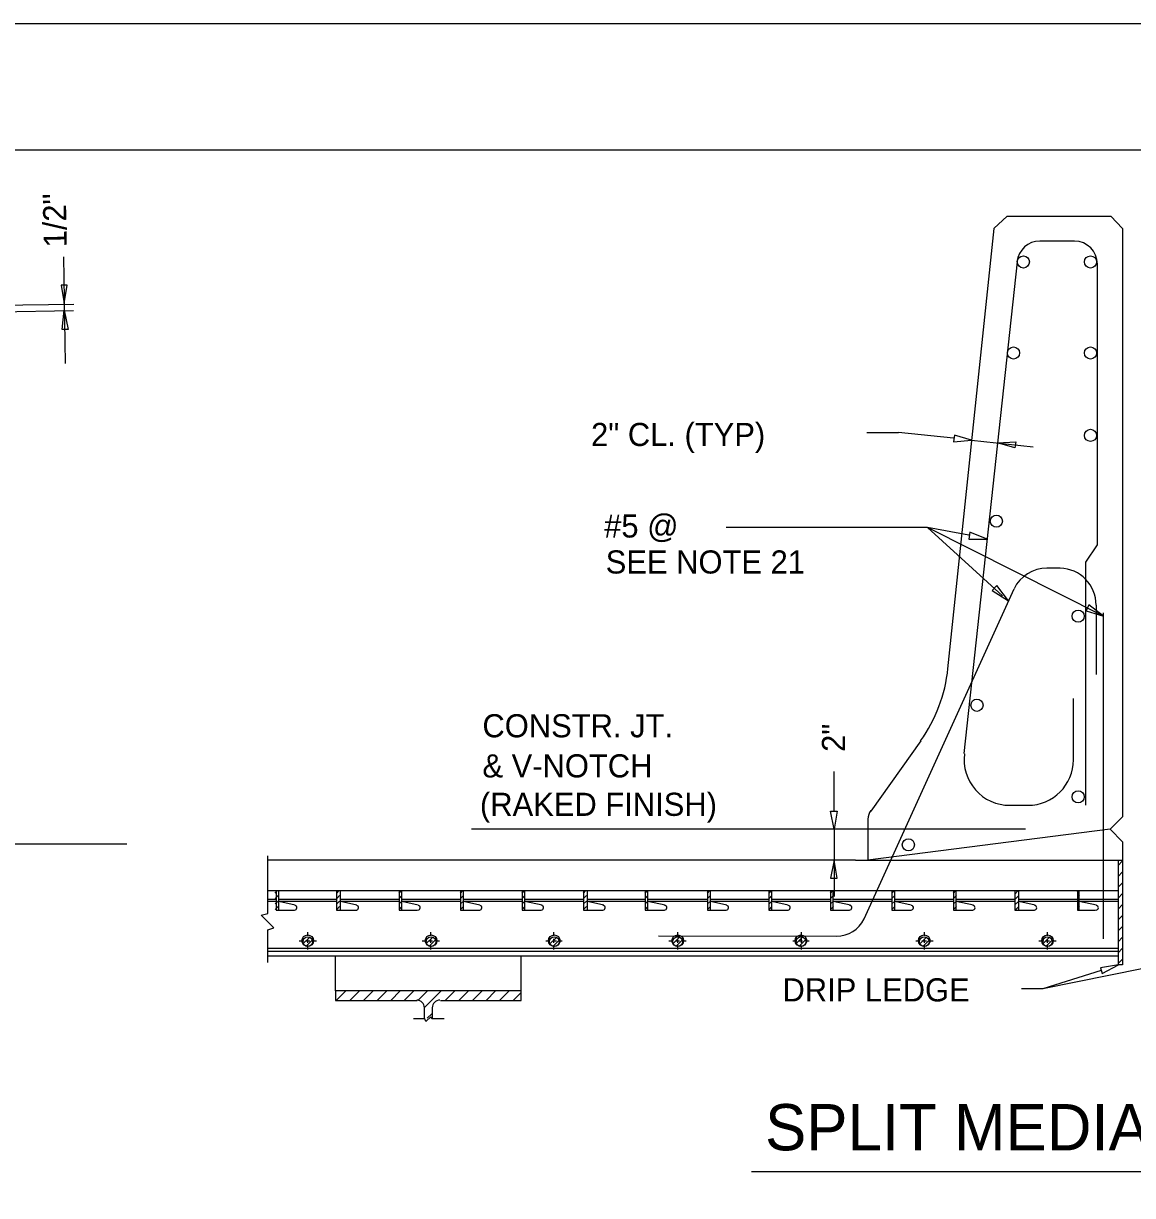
# Model space of a CAD drawing. Extents: x -24512 to -22484, y 4569 to 6351.
# Drawn here: x -23889.5 to -23745.6, y 6199 to 6351 of the extents above; entities that cross this region are included whole.
import ezdxf

# ---------------------------------------------------------------- set-up
doc = ezdxf.new("R2010")
doc.units = 0
for name, color, linetype in [('10', 7, 'Continuous'), ('11', 7, 'Continuous'), ('2', 7, 'Continuous'), ('4', 7, 'Continuous'), ('5', 7, 'Continuous'), ('8', 7, 'Continuous'), ('PLT-BNDY', 7, 'Continuous')]:
    doc.layers.add(name, color=color, linetype=linetype)

# ---------------------------------------------------------------- blocks, each defined once
blk = doc.blocks.new('_X')
at = {"layer": '4'}
for p, q in [((63.193375, 24.416625), (63.299125, 24.522375)), ((63.193375, 24.1315), (63.3445, 24.282625)), ((63.193375, 23.846375), (63.3445, 23.9975)), ((63.193375, 23.56125), (63.3445, 23.712375))]:
    blk.add_line(p, q, dxfattribs=at)
blk = doc.blocks.new('JUQ000')
at = {"layer": '4'}
for p, q in [((71.0975, 21.771125), (71.421875, 22.095625)), ((71.237875, 21.6265), (71.566625, 21.95525))]:
    blk.add_line(p, q, dxfattribs=at)
blk = doc.blocks.new('JUQ003')
at = {"layer": '4'}
for p, q in [((89.35625, 63.69525), (89.860375, 64.19925)), ((90.069125, 63.69525), (90.573125, 64.19925)), ((90.781875, 63.69525), (91.285875, 64.19925)), ((91.49475, 63.69525), (91.99875, 64.19925)), ((92.2075, 63.69525), (92.7115, 64.19925)), ((92.920375, 63.69525), (93.424375, 64.19925)), ((93.628875, 63.691), (94.137125, 64.19925)), ((93.972625, 63.321875), (94.85, 64.19925)), ((95.05875, 63.69525), (95.56275, 64.19925)), ((95.7715, 63.69525), (96.275625, 64.19925)), ((96.484375, 63.69525), (96.988375, 64.19925)), ((97.197125, 63.69525), (97.70125, 64.19925)), ((97.91, 63.69525), (98.414, 64.19925)), ((98.62275, 63.69525), (99.014, 64.0865)), ((94.121125, 62.757625), (94.377, 63.013375))]:
    blk.add_line(p, q, dxfattribs=at)
blk = doc.blocks.new('JUQ007')
at = {"layer": '4'}
for p, q in [((153.103125, 337.29275), (153.30475, 337.494375)), ((153.103125, 336.7225), (153.30475, 336.924125)), ((153.103125, 336.15225), (153.30475, 336.353875)), ((153.103125, 335.582), (153.30475, 335.783625)), ((153.103125, 335.01175), (153.30475, 335.213375)), ((153.103125, 334.4415), (153.30475, 334.643125)), ((153.103125, 333.87125), (153.30475, 334.072875)), ((153.103125, 333.301), (153.30475, 333.502625)), ((153.103125, 332.73075), (153.30475, 332.932375)), ((153.103125, 332.1605), (153.30475, 332.362125))]:
    blk.add_line(p, q, dxfattribs=at)

msp = doc.modelspace()

# ---------------------------------------------------------------- linework, layer by layer
at = {"layer": '10'}
for p, q in [((-23884.06, 6306.94), (-23884.3, 6320.75)), ((-23903.14, 6314.4), (-23883, 6314.61)), ((-23903.14, 6313.41), (-23883.01, 6313.81)), ((-23780.08, 6297.99), (-23775.95, 6297.99)), ((-23768.84, 6297.25), (-23775.95, 6297.99)), ((-23766.48, 6296.96), (-23758.49, 6296.12)), ((-23772.2, 6285.65), (-23798.31, 6285.65)), ((-23766.84, 6284.65), (-23772.2, 6285.65)), ((-23762.48, 6276.8), (-23772.2, 6285.65)), ((-23749.34, 6274.15), (-23772.2, 6285.65)), ((-23754.96, 6280.39), (-23756.7, 6280.39)), ((-23784.3, 6248.87), (-23784.3, 6253.98)), ((-23759.49, 6246.5), (-23831.39, 6246.5)), ((-23784.3, 6246.5), (-23784.3, 6237.77)), ((-23852.63, 6232.66), (-23852.63, 6233.16)), ((-23836.67, 6232.66), (-23836.67, 6233.16)), ((-23820.71, 6232.66), (-23820.71, 6233.16)), ((-23804.62, 6232.66), (-23804.62, 6233.16)), ((-23788.54, 6232.66), (-23788.54, 6233.16)), ((-23772.58, 6232.66), (-23772.58, 6233.16)), ((-23756.62, 6232.66), (-23756.62, 6233.16)), ((-23853.75, 6232.03), (-23853.13, 6232.03)), ((-23852.88, 6232.03), (-23852.38, 6232.03)), ((-23852.63, 6231.78), (-23852.63, 6232.28)), ((-23852.13, 6232.03), (-23851.51, 6232.03)), ((-23837.79, 6232.03), (-23837.17, 6232.03)), ((-23836.92, 6232.03), (-23836.42, 6232.03)), ((-23836.67, 6231.78), (-23836.67, 6232.28)), ((-23836.04, 6232.03), (-23835.55, 6232.03)), ((-23821.71, 6232.03), (-23821.21, 6232.03)), ((-23820.83, 6232.03), (-23820.33, 6232.03)), ((-23820.71, 6231.78), (-23820.71, 6232.28)), ((-23819.96, 6232.03), (-23819.59, 6232.03)), ((-23805.75, 6232.03), (-23805.25, 6232.03)), ((-23804.87, 6232.03), (-23804.37, 6232.03)), ((-23804.62, 6231.78), (-23804.62, 6232.28)), ((-23804, 6232.03), (-23803.5, 6232.03)), ((-23789.66, 6232.03), (-23789.16, 6232.03)), ((-23788.91, 6232.03), (-23788.41, 6232.03)), ((-23788.54, 6231.78), (-23788.54, 6232.28)), ((-23788.04, 6232.03), (-23787.54, 6232.03)), ((-23773.7, 6232.03), (-23773.2, 6232.03)), ((-23772.95, 6232.03), (-23772.33, 6232.03)), ((-23772.58, 6231.78), (-23772.58, 6232.28)), ((-23772.08, 6232.03), (-23771.46, 6232.03)), ((-23757.74, 6232.03), (-23757.12, 6232.03)), ((-23756.87, 6232.03), (-23756.37, 6232.03)), ((-23756.62, 6231.78), (-23756.62, 6232.28)), ((-23756.12, 6232.03), (-23755.5, 6232.03)), ((-23852.63, 6230.91), (-23852.63, 6231.41)), ((-23836.67, 6230.91), (-23836.67, 6231.41)), ((-23820.71, 6230.91), (-23820.71, 6231.41)), ((-23804.62, 6230.91), (-23804.62, 6231.41)), ((-23788.54, 6230.91), (-23788.54, 6231.41)), ((-23772.58, 6230.91), (-23772.58, 6231.41)), ((-23756.62, 6230.91), (-23756.62, 6231.41)), ((-23744.15, 6228.42), (-23757.24, 6225.8)), ((-23749.64, 6228.17), (-23757.24, 6225.8)), ((-23757.24, 6225.8), (-23759.99, 6225.8))]:
    msp.add_line(p, q, dxfattribs=at)
for points in [[(-23883.86, 6317.08), (-23884.61, 6317.08), (-23884.24, 6314.71)], [(-23883.74, 6311.35), (-23884.49, 6311.35), (-23884.24, 6313.84)], [(-23768.71, 6297.62), (-23768.84, 6296.75), (-23766.47, 6297)], [(-23760.73, 6296.75), (-23760.86, 6296), (-23763.1, 6296.62)], [(-23766.72, 6285.03), (-23766.84, 6284.15), (-23764.47, 6284.15)], [(-23763.18, 6278.12), (-23763.81, 6277.49), (-23761.69, 6276.12)], [(-23751.25, 6275.63), (-23751.61, 6274.82), (-23749.34, 6274.16)], [(-23784.8, 6248.87), (-23783.93, 6248.87), (-23784.3, 6246.5)], [(-23784.8, 6240.14), (-23783.93, 6240.14), (-23784.3, 6242.51)], [(-23749.76, 6228.54), (-23749.51, 6227.79), (-23747.39, 6228.92)]]:
    msp.add_lwpolyline(points, close=True, dxfattribs=at)
for centre, radius, start, end in [((-23757.6, 6319.81), 3, 90, 173.8386), ((-23753.14, 6319.81), 3, 0, 90), ((-23756.66, 6275.59), 4.8, 90.4711, 153.9247), ((-23755.12, 6275.59), 4.8, 0, 88.1461), ((-23784.01, 6236.63), 4, 269.938, 333.8946)]:
    msp.add_arc(centre, radius, start, end, dxfattribs=at)
at = {"layer": '11'}
for p, q in [((-23876.11, 6244.57), (-24132.21, 6244.57)), ((-23674.47, 6202.06), (-23795.04, 6202.06))]:
    msp.add_line(p, q, dxfattribs=at)
at = {"layer": '2'}
msp.add_line((-24137.79, 6334.63), (-23353.75, 6334.63), dxfattribs=at)
at = {"layer": '4'}
for p, q in [((-23760.86, 6238.1), (-23760.46, 6238.5)), ((-23760.86, 6237.39), (-23760.35, 6237.9)), ((-23752.75, 6238.35), (-23752.6, 6238.5)), ((-23752.75, 6237.64), (-23752.49, 6237.9)), ((-23760.86, 6236.68), (-23760.35, 6237.19)), ((-23760.72, 6236.11), (-23760.35, 6236.49)), ((-23752.75, 6236.93), (-23752.49, 6237.19)), ((-23752.75, 6236.22), (-23752.49, 6236.49))]:
    msp.add_line(p, q, dxfattribs=at)
at = {"layer": '5'}
for p, q in [((-23781.56, 6242.51), (-23857.76, 6242.51)), ((-23856.74, 6238.52), (-23857.76, 6238.52)), ((-23848.89, 6238.52), (-23856.37, 6238.52)), ((-23840.78, 6238.52), (-23848.39, 6238.52)), ((-23832.8, 6238.52), (-23840.41, 6238.52)), ((-23824.82, 6238.52), (-23832.43, 6238.52)), ((-23816.84, 6238.52), (-23824.45, 6238.52)), ((-23808.86, 6238.52), (-23816.34, 6238.52)), ((-23800.76, 6238.52), (-23808.49, 6238.52)), ((-23792.78, 6238.52), (-23800.38, 6238.52)), ((-23784.8, 6238.52), (-23792.4, 6238.52)), ((-23776.82, 6238.52), (-23784.42, 6238.52)), ((-23768.84, 6238.52), (-23776.44, 6238.52)), ((-23760.86, 6238.52), (-23768.46, 6238.52)), ((-23752.75, 6238.52), (-23760.36, 6238.52)), ((-23747.39, 6238.52), (-23752.5, 6238.52)), ((-23856.74, 6237.4), (-23857.76, 6237.4)), ((-23856.74, 6237.15), (-23857.76, 6237.15)), ((-23848.89, 6237.4), (-23856.37, 6237.4)), ((-23848.89, 6237.15), (-23856.37, 6237.15)), ((-23854.25, 6236.65), (-23856.37, 6237.15)), ((-23856.37, 6236.02), (-23854.37, 6236.02)), ((-23840.78, 6237.4), (-23848.39, 6237.4)), ((-23840.78, 6237.15), (-23848.39, 6237.15)), ((-23846.27, 6236.65), (-23848.39, 6237.15)), ((-23848.39, 6236.02), (-23846.27, 6236.02)), ((-23832.8, 6237.4), (-23840.41, 6237.4)), ((-23832.8, 6237.15), (-23840.41, 6237.15)), ((-23838.29, 6236.65), (-23840.41, 6237.15)), ((-23840.41, 6236.02), (-23838.41, 6236.02)), ((-23824.82, 6237.4), (-23832.43, 6237.4)), ((-23824.82, 6237.15), (-23832.43, 6237.15)), ((-23830.31, 6236.65), (-23832.43, 6237.15)), ((-23832.43, 6236.02), (-23830.31, 6236.02)), ((-23816.84, 6237.4), (-23824.45, 6237.4)), ((-23816.84, 6237.15), (-23824.45, 6237.15)), ((-23822.2, 6236.65), (-23824.45, 6237.15)), ((-23824.45, 6236.02), (-23822.33, 6236.02)), ((-23808.86, 6237.4), (-23816.34, 6237.4)), ((-23808.86, 6237.15), (-23816.34, 6237.15)), ((-23814.22, 6236.65), (-23816.34, 6237.15)), ((-23816.34, 6236.02), (-23814.35, 6236.02)), ((-23800.76, 6237.4), (-23808.49, 6237.4)), ((-23800.76, 6237.15), (-23808.49, 6237.15)), ((-23806.24, 6236.65), (-23808.49, 6237.15)), ((-23808.49, 6236.02), (-23806.37, 6236.02)), ((-23792.78, 6237.4), (-23800.38, 6237.4)), ((-23792.78, 6237.15), (-23800.38, 6237.15)), ((-23798.26, 6236.65), (-23800.38, 6237.15)), ((-23800.38, 6236.02), (-23798.39, 6236.02)), ((-23784.8, 6237.4), (-23792.4, 6237.4)), ((-23784.8, 6237.15), (-23792.4, 6237.15)), ((-23790.28, 6236.65), (-23792.4, 6237.15)), ((-23792.4, 6236.02), (-23790.28, 6236.02)), ((-23776.82, 6237.4), (-23784.42, 6237.4)), ((-23776.82, 6237.15), (-23784.42, 6237.15)), ((-23782.18, 6236.65), (-23784.42, 6237.15)), ((-23784.42, 6236.02), (-23782.3, 6236.02)), ((-23768.84, 6237.4), (-23776.44, 6237.4)), ((-23768.84, 6237.15), (-23776.44, 6237.15)), ((-23774.32, 6236.65), (-23776.44, 6237.15)), ((-23776.44, 6236.02), (-23774.32, 6236.02)), ((-23760.86, 6237.4), (-23768.46, 6237.4)), ((-23760.86, 6237.15), (-23768.46, 6237.15)), ((-23766.22, 6236.65), (-23768.46, 6237.15)), ((-23768.46, 6236.02), (-23766.34, 6236.02)), ((-23752.75, 6237.4), (-23760.36, 6237.4)), ((-23752.75, 6237.15), (-23760.36, 6237.15)), ((-23758.24, 6236.65), (-23760.36, 6237.15)), ((-23760.36, 6236.02), (-23758.36, 6236.02)), ((-23747.39, 6237.4), (-23752.5, 6237.4)), ((-23747.39, 6237.15), (-23752.5, 6237.15)), ((-23750.26, 6236.65), (-23752.5, 6237.15)), ((-23752.5, 6236.02), (-23750.38, 6236.02)), ((-23747.39, 6231.04), (-23857.76, 6231.04)), ((-23747.39, 6230.66), (-23857.76, 6230.66)), ((-23747.39, 6230.04), (-23857.76, 6230.04)), ((-23849.01, 6225.55), (-23849.01, 6230.04)), ((-23824.95, 6225.55), (-23824.95, 6230.04)), ((-23824.95, 6225.55), (-23849.01, 6225.55)), ((-23849.01, 6225.55), (-23849.01, 6224.3)), ((-23824.95, 6224.3), (-23824.95, 6225.55)), ((-23849.01, 6224.3), (-23838.41, 6224.3)), ((-23835.42, 6224.3), (-23824.95, 6224.3)), ((-23837.54, 6223.31), (-23837.54, 6221.93)), ((-23836.42, 6221.93), (-23836.42, 6223.31)), ((-23837.54, 6221.93), (-23838.91, 6221.93)), ((-23834.92, 6221.93), (-23836.42, 6221.93))]:
    msp.add_line(p, q, dxfattribs=at)
for points in [[(-23857.8, 6229.23), (-23857.8, 6233.47), (-23857.05, 6233.72), (-23858.67, 6235.34), (-23857.8, 6235.59), (-23857.8, 6243.07)], [(-23836.42, 6221.93), (-23836.54, 6221.93), (-23836.67, 6222.18), (-23837.29, 6221.56), (-23837.42, 6221.93), (-23837.54, 6221.93)]]:
    msp.add_lwpolyline(points, dxfattribs=at)
for points in [[(-23746.89, 6228.92), (-23747.39, 6228.92), (-23747.39, 6242.51), (-23746.89, 6242.51)], [(-23856.74, 6238.52), (-23856.74, 6236.02), (-23856.37, 6236.02), (-23856.37, 6238.52)], [(-23848.89, 6238.52), (-23848.89, 6236.02), (-23848.39, 6236.02), (-23848.39, 6238.52)], [(-23840.78, 6238.52), (-23840.78, 6236.02), (-23840.41, 6236.02), (-23840.41, 6238.52)], [(-23832.8, 6238.52), (-23832.8, 6236.02), (-23832.43, 6236.02), (-23832.43, 6238.52)], [(-23824.82, 6238.52), (-23824.82, 6236.02), (-23824.45, 6236.02), (-23824.45, 6238.52)], [(-23816.84, 6238.52), (-23816.84, 6236.02), (-23816.34, 6236.02), (-23816.34, 6238.52)], [(-23808.86, 6238.52), (-23808.86, 6236.02), (-23808.49, 6236.02), (-23808.49, 6238.52)], [(-23800.76, 6238.52), (-23800.76, 6236.02), (-23800.38, 6236.02), (-23800.38, 6238.52)], [(-23792.78, 6238.52), (-23792.78, 6236.02), (-23792.4, 6236.02), (-23792.4, 6238.52)], [(-23784.8, 6238.52), (-23784.8, 6236.02), (-23784.42, 6236.02), (-23784.42, 6238.52)], [(-23776.82, 6238.52), (-23776.82, 6236.02), (-23776.44, 6236.02), (-23776.44, 6238.52)], [(-23768.84, 6238.52), (-23768.84, 6236.02), (-23768.46, 6236.02), (-23768.46, 6238.52)], [(-23760.86, 6238.52), (-23760.86, 6236.02), (-23760.36, 6236.02), (-23760.36, 6238.52)], [(-23752.75, 6238.52), (-23752.75, 6236.02), (-23752.5, 6236.02), (-23752.5, 6238.52)]]:
    msp.add_lwpolyline(points, close=True, dxfattribs=at)
for centre, radius in [((-23852.63, 6232.05), 0.75), ((-23852.63, 6231.92), 0.625), ((-23836.63, 6232.05), 0.75), ((-23836.63, 6231.92), 0.625), ((-23820.63, 6232.05), 0.75), ((-23820.63, 6231.92), 0.625), ((-23804.62, 6232.05), 0.75), ((-23804.62, 6231.92), 0.625), ((-23788.62, 6232.05), 0.75), ((-23788.62, 6231.92), 0.625), ((-23772.62, 6232.05), 0.75), ((-23772.62, 6231.92), 0.625), ((-23756.62, 6232.05), 0.75), ((-23756.62, 6231.92), 0.625)]:
    msp.add_circle(centre, radius, dxfattribs=at)
for centre, radius, start, end in [((-23854.34, 6236.33), 0.305, 271.249, 76.5605), ((-23846.34, 6236.33), 0.305, 271.249, 76.5605), ((-23838.34, 6236.33), 0.305, 271.249, 76.5605), ((-23830.34, 6236.33), 0.305, 271.249, 76.5605), ((-23822.34, 6236.33), 0.305, 271.249, 76.5605), ((-23814.34, 6236.33), 0.305, 271.249, 76.5605), ((-23806.34, 6236.33), 0.305, 271.249, 76.5605), ((-23798.33, 6236.33), 0.305, 271.249, 76.5605), ((-23790.33, 6236.33), 0.305, 271.249, 76.5605), ((-23782.33, 6236.33), 0.305, 271.249, 76.5605), ((-23774.33, 6236.33), 0.305, 271.249, 76.5605), ((-23766.33, 6236.33), 0.305, 271.249, 76.5605), ((-23758.33, 6236.33), 0.305, 271.249, 76.5605), ((-23750.33, 6236.33), 0.305, 271.249, 76.5605), ((-23838.48, 6223.33), 1, 0, 90), ((-23835.48, 6223.33), 1, 90, 180)]:
    msp.add_arc(centre, radius, start, end, dxfattribs=at)
at = {"layer": '8'}
for p, q in [((-23753.14, 6322.81), (-23757.6, 6322.81)), ((-23760.58, 6320.13), (-23767.47, 6256.35)), ((-23750.14, 6283.41), (-23750.14, 6319.81)), ((-23751.63, 6249.61), (-23751.63, 6280.29)), ((-23780.42, 6234.87), (-23760.97, 6277.7)), ((-23750.32, 6275.59), (-23750.32, 6266.57)), ((-23749.34, 6232.27), (-23749.34, 6274.58)), ((-23753.25, 6255.48), (-23753.25, 6263.46)), ((-23761.48, 6249.61), (-23759.11, 6249.61)), ((-23807.12, 6232.66), (-23784.01, 6232.63))]:
    msp.add_line(p, q, dxfattribs=at)
msp.add_lwpolyline([(-23751.63, 6280.29), (-23751.63, 6281.16), (-23750.14, 6283.41)], dxfattribs=at)
for centre in [(-23759.76, 6320.1), (-23751.05, 6320.1), (-23761.03, 6308.29), (-23751.05, 6308.29), (-23751.05, 6297.6), (-23763.26, 6286.48), (-23752.64, 6274.15), (-23765.78, 6262.59), (-23752.64, 6250.71), (-23774.68, 6244.48)]:
    msp.add_circle(centre, 0.788, dxfattribs=at)
for centre, start, end in [((-23761.53, 6255.52), 172.5603, 270), ((-23759.17, 6255.52), 270, 0)]:
    msp.add_arc(centre, 5.91, start, end, dxfattribs=at)
at = {"layer": 'PLT-BNDY'}
for p, q in [((-23763.6, 6324.43), (-23761.86, 6326.05)), ((-23761.86, 6326.05), (-23748.39, 6326.05)), ((-23746.89, 6324.43), (-23748.39, 6326.05)), ((-23763.6, 6324.43), (-23769.59, 6267.32)), ((-23746.89, 6324.43), (-23746.89, 6248.12)), ((-23773.08, 6257.97), (-23779.56, 6248.87)), ((-23779.94, 6247.87), (-23779.94, 6242.51)), ((-23746.89, 6248.12), (-23748.51, 6246.5)), ((-23748.51, 6246.5), (-23779.94, 6242.51)), ((-23746.89, 6244.88), (-23748.51, 6246.5)), ((-23746.89, 6244.88), (-23746.89, 6242.51)), ((-23781.56, 6242.51), (-23746.89, 6242.51))]:
    msp.add_line(p, q, dxfattribs=at)
msp.add_lwpolyline([(-23338.75, 5757.04), (-24179.75, 5757.04), (-24179.75, 6351.04), (-23338.75, 6351.04)], close=True, dxfattribs=at)
for centre, radius, start, end in [((-23789.12, 6269.43), 19.69, 324.4623, 354.0094), ((-23777.95, 6247.8), 1.97, 144.4623, 180)]:
    msp.add_arc(centre, radius, start, end, dxfattribs=at)

# ---------------------------------------------------------------- block references
at = {"layer": '4'}
for name, p, xscale, yscale in [('JUQ007', (-24127.18, 5405.23), 2.4803976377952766, 2.4803976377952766), ('_X', (-24013.6, 6177.67), 2.4803976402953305, 2.4803976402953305), ('_X', (-24005.62, 6177.67), 2.4803976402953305, 2.4803976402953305), ('_X', (-23997.52, 6177.67), 2.4803976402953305, 2.4803976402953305), ('_X', (-23989.54, 6177.67), 2.4803976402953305, 2.4803976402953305), ('_X', (-23981.56, 6177.67), 2.4803976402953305, 2.4803976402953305), ('_X', (-23973.58, 6177.67), 2.4803976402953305, 2.4803976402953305), ('_X', (-23965.6, 6177.67), 2.4803976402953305, 2.4803976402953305), ('_X', (-23957.49, 6177.67), 2.4803976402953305, 2.4803976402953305), ('_X', (-23949.51, 6177.67), 2.4803976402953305, 2.4803976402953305), ('_X', (-23941.53, 6177.67), 2.4803976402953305, 2.4803976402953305), ('_X', (-23933.55, 6177.67), 2.4803976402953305, 2.4803976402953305), ('_X', (-23925.57, 6177.67), 2.4803976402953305, 2.4803976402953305), ('JUQ000', (-24029.56, 6177.67), 2.4803976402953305, 2.4803976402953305), ('JUQ000', (-24013.6, 6177.67), 2.4803976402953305, 2.4803976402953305), ('JUQ000', (-23997.52, 6177.67), 2.4803976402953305, 2.4803976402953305), ('JUQ000', (-23981.56, 6177.67), 2.4803976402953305, 2.4803976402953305), ('JUQ000', (-23965.6, 6177.67), 2.4803976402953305, 2.4803976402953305), ('JUQ000', (-23949.51, 6177.67), 2.4803976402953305, 2.4803976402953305), ('JUQ000', (-23933.55, 6177.67), 2.4803976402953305, 2.4803976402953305), ('JUQ003', (-24070.58, 6066.32), 2.4803976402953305, 2.4803976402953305)]:
    msp.add_blockref(name, p, dxfattribs=dict(at, xscale=xscale, yscale=yscale))

# ---------------------------------------------------------------- texts
at = {"layer": '10'}
for s, rotation, p in [('1/2"', 91.0964, (-23883.89, 6322.02)), ('2"', 90, (-23782.9, 6256.54))]:
    msp.add_text(s, height=3, rotation=rotation, dxfattribs=at).set_placement(p)
for s, p in [('2" CL. (TYP)', (-23815.86, 6296.22)), ('#5 @', (-23814.16, 6284.35)), ('SEE NOTE 21', (-23813.96, 6279.68)), ('CONSTR. JT.', (-23829.96, 6258.43)), ('& V-NOTCH', (-23829.96, 6253.23)), ('(RAKED FINISH)', (-23830.28, 6248.24)), ('DRIP LEDGE', (-23791.02, 6224.17))]:
    msp.add_text(s, height=3, dxfattribs=at).set_placement(p)
at = {"layer": '11'}
msp.add_text('SPLIT MEDIAN BARRIER', height=6.0008, dxfattribs=at).set_placement((-23793.28, 6204.85))

doc.saveas('drawing.dxf')
